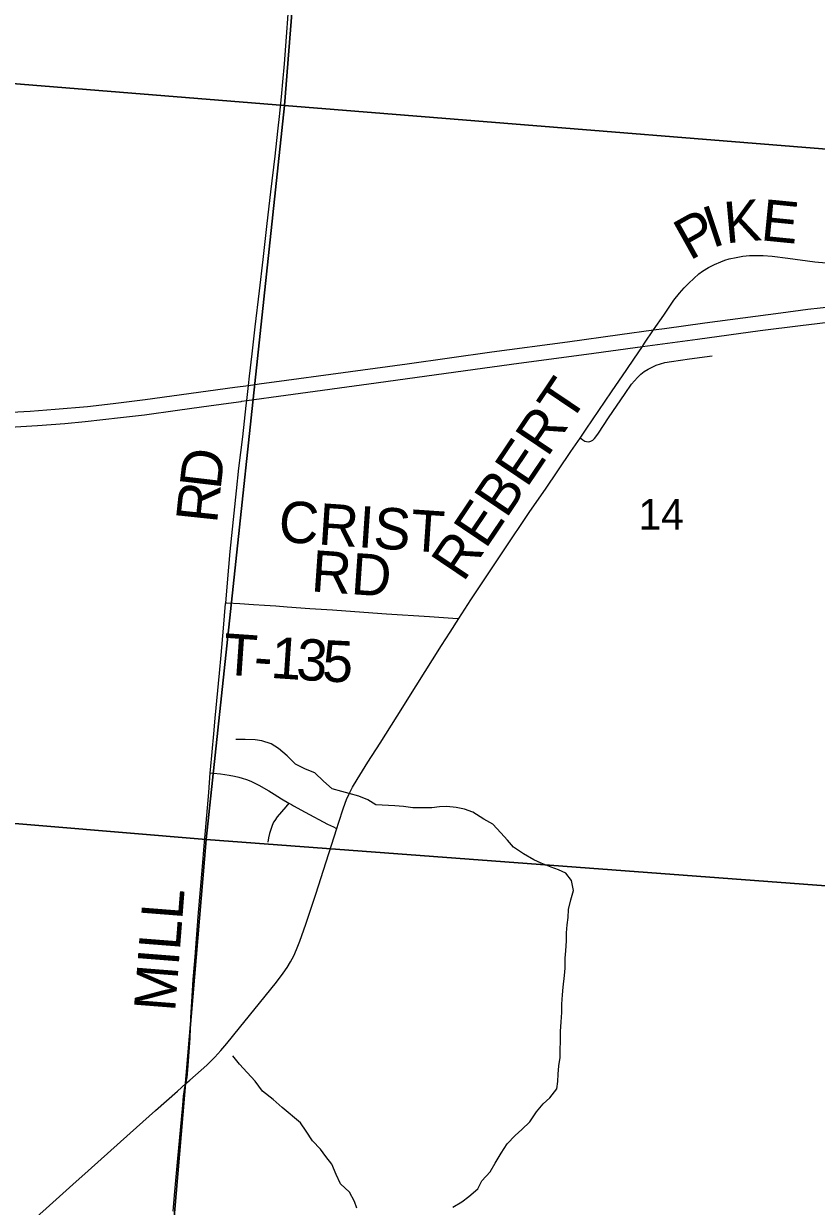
# Model space of a CAD drawing. Extents: x 0 to 34, y 0 to 22.
# Drawn here: x 5.632 to 6.722, y 14.717 to 16.342 of the extents above; entities that cross this region are included whole.
import ezdxf

# ---------------------------------------------------------------- set-up
doc = ezdxf.new("R2010")
doc.units = 0
for name, color, linetype in [('GM_X_County_Road', 7, 'Continuous'), ('GM_X_County_Road_Text', 7, 'Continuous'), ('GM_X_Interstate_Route', 7, 'Continuous'), ('GM_X_Minor_River', 7, 'Continuous'), ('GM_X_Section', 7, 'Continuous'), ('GM_X_Section_Text', 7, 'Continuous'), ('GM_X_Township_Road', 7, 'Continuous'), ('GM_X_Township_Road_Text', 7, 'Continuous')]:
    doc.layers.add(name, color=color, linetype=linetype)

msp = doc.modelspace()

# ---------------------------------------------------------------- linework, layer by layer
at = {"layer": 'GM_X_County_Road'}
for points in [[(6.4706, 15.8808), (6.4825, 15.8983), (6.4855, 15.9027), (6.4979, 15.9209), (6.5118, 15.9412), (6.5259, 15.9617), (6.5336, 15.9715), (6.5397, 15.9786), (6.5462, 15.9854), (6.553, 15.9918), (6.5602, 15.9978), (6.5652, 16.0015), (6.5732, 16.0065), (6.5815, 16.0109), (6.5901, 16.0147), (6.596, 16.0168), (6.602, 16.0186), (6.6112, 16.0206), (6.6204, 16.0221), (6.6298, 16.023), (6.6392, 16.0233), (6.6485, 16.0231), (6.661, 16.0221), (6.6826, 16.0195), (6.7196, 16.0146), (6.735, 16.0131)], [(6.3967, 15.7725), (6.405, 15.7846), (6.44, 15.8359), (6.461, 15.8667), (6.4706, 15.8808)], [(6.2302, 15.5245), (6.2468, 15.5502), (6.2623, 15.5735), (6.2776, 15.5969), (6.2914, 15.6176), (6.3279, 15.6717), (6.3491, 15.7024), (6.3839, 15.7538), (6.3967, 15.7725)], [(6.0623, 15.2362), (6.0646, 15.2436), (6.0714, 15.2643), (6.0758, 15.276), (6.0796, 15.2845), (6.0838, 15.2929), (6.0902, 15.3036), (6.1051, 15.3273), (6.1218, 15.3535), (6.1451, 15.3902), (6.1716, 15.4323), (6.2064, 15.4875), (6.2181, 15.5058), (6.2302, 15.5245)], [(5.8549, 14.8856), (5.8604, 14.8905), (5.8835, 14.9112), (5.8946, 14.922), (5.903, 14.9311), (5.911, 14.9406), (5.9285, 14.9624), (5.9559, 14.9961), (5.9793, 15.0252), (5.9887, 15.0375), (5.994, 15.0451), (5.9988, 15.053), (6.0031, 15.0612), (6.007, 15.0697), (6.0115, 15.0812), (6.0198, 15.1046), (6.0334, 15.1459), (6.0478, 15.1903), (6.0623, 15.2362)], [(5.2834, 14.3675), (5.3102, 14.3924), (5.3892, 14.4668), (5.4048, 14.4812), (5.4275, 14.5022), (5.4459, 14.519), (5.4779, 14.5483), (5.5181, 14.585), (5.5561, 14.6191), (5.5885, 14.6481), (5.6209, 14.6768), (5.6627, 14.7139), (5.6765, 14.7264), (5.6996, 14.7472), (5.7203, 14.766), (5.7783, 14.8176), (5.8131, 14.8486), (5.8434, 14.8753), (5.8549, 14.8856)]]:
    msp.add_lwpolyline(points, dxfattribs=at)
at = {"layer": 'GM_X_Interstate_Route'}
msp.add_line((5.9308, 15.8227), (5.9318, 15.8229), dxfattribs=at)
for points in [[(5.941, 15.8448), (5.9558, 15.8468), (5.9931, 15.852), (6.0541, 15.8602), (6.1592, 15.8746), (6.2755, 15.8908), (6.3793, 15.9048), (6.4515, 15.9148), (6.4979, 15.9209), (6.5128, 15.9229), (6.5683, 15.9306), (6.6728, 15.9446), (6.7098, 15.9493), (6.7777, 15.9568), (6.8405, 15.9634), (6.9002, 15.969), (6.9047, 15.9693)], [(5.9318, 15.8229), (5.9385, 15.8238), (5.9922, 15.8313), (6.1163, 15.8483), (6.2392, 15.8653), (6.3125, 15.8751), (6.4054, 15.8879), (6.4825, 15.8983), (6.5584, 15.9085), (6.6446, 15.92), (6.7, 15.9272), (6.7494, 15.9331), (6.8019, 15.9388), (6.8798, 15.9466), (6.9075, 15.9489)], [(5.5978, 15.807), (5.6405, 15.8094), (5.6749, 15.8119), (5.7194, 15.816), (5.755, 15.8197), (5.7987, 15.8253), (5.9222, 15.8423), (5.941, 15.8448)], [(5.6127, 15.7873), (5.6507, 15.7897), (5.6883, 15.7925), (5.7162, 15.7953), (5.7648, 15.8005), (5.7978, 15.8045), (5.8431, 15.8107), (5.8763, 15.8153), (5.9133, 15.8203), (5.9308, 15.8227)]]:
    msp.add_lwpolyline(points, dxfattribs=at)
at = {"layer": 'GM_X_Minor_River'}
for points in [[(6.1162, 15.2687), (6.105, 15.2753), (6.0925, 15.2804), (6.0793, 15.284), (6.0694, 15.2868), (6.0558, 15.2907), (6.0438, 15.3011), (6.0321, 15.3126), (6.0193, 15.3177), (6.0053, 15.3243), (5.994, 15.3359), (5.982, 15.3459), (5.9722, 15.3524), (5.9594, 15.3564), (5.9499, 15.358), (5.9362, 15.3582), (5.9233, 15.3583)], [(6.2219, 14.7158), (6.234, 14.7233), (6.2439, 14.7304), (6.2561, 14.741), (6.2619, 14.7519), (6.2733, 14.7643), (6.2802, 14.7764), (6.2883, 14.79), (6.2967, 14.8028), (6.3074, 14.8145), (6.3169, 14.8228), (6.3275, 14.8333), (6.3367, 14.8469), (6.3459, 14.8578), (6.3554, 14.8661), (6.365, 14.8786), (6.3662, 14.8884), (6.3666, 14.8986), (6.3678, 14.91), (6.3694, 14.9217), (6.3695, 14.9331), (6.37, 14.943), (6.3701, 14.9574), (6.3709, 14.9706), (6.3718, 14.9835), (6.3719, 14.9949), (6.3727, 15.0074), (6.3736, 15.018), (6.3756, 15.0343), (6.3764, 15.0441), (6.3765, 15.0582), (6.3773, 15.068), (6.3782, 15.0817), (6.3783, 15.093), (6.3791, 15.1036), (6.3803, 15.1139), (6.3808, 15.1249), (6.3839, 15.1381), (6.3878, 15.151), (6.3852, 15.1646), (6.377, 15.1746), (6.3672, 15.1792), (6.357, 15.183), (6.3434, 15.1885), (6.3333, 15.1931), (6.3189, 15.2015), (6.3054, 15.2103), (6.2968, 15.2199), (6.2878, 15.2302), (6.2769, 15.242), (6.2645, 15.2489), (6.2494, 15.2585), (6.2377, 15.2628), (6.2264, 15.2651), (6.2135, 15.2664), (6.2037, 15.2657), (6.1931, 15.2646), (6.1806, 15.2643), (6.167, 15.2644), (6.1541, 15.2661), (6.142, 15.2673), (6.1162, 15.2687)], [(6.0897, 14.7144), (6.0868, 14.7239), (6.0797, 14.7365), (6.0673, 14.748), (6.0614, 14.761), (6.0555, 14.7751), (6.0473, 14.7855), (6.0398, 14.7958), (6.0289, 14.807), (6.02, 14.8204), (6.0122, 14.8318), (5.9873, 14.853), (5.9749, 14.8638), (5.9603, 14.8753), (5.9502, 14.8891), (5.9389, 14.901), (5.9284, 14.9122), (5.9195, 14.9237)]]:
    msp.add_lwpolyline(points, dxfattribs=at)
at = {"layer": 'GM_X_Section'}
for points in [[(5.0487, 17.3219), (6.0711, 17.2462), (5.9902, 16.2292), (4.9634, 16.3122)], [(6.0711, 17.2462), (7.0855, 17.1656), (6.992, 16.1486), (5.9902, 16.2292)], [(4.9634, 16.3122), (5.9902, 16.2292), (5.8825, 15.2209), (4.8743, 15.3051)], [(5.9902, 16.2292), (6.992, 16.1486), (6.9002, 15.1449), (5.8825, 15.2209)], [(4.8743, 15.3051), (5.8825, 15.2209), (5.7982, 14.227), (4.7952, 14.3092), (4.7835, 14.3098)], [(5.8825, 15.2209), (6.9002, 15.1449), (6.8099, 14.1356), (5.8205, 14.2252), (5.7982, 14.227)]]:
    msp.add_lwpolyline(points, close=True, dxfattribs=at)
at = {"layer": 'GM_X_Township_Road'}
for points in [[(5.9096, 15.5462), (5.9139, 15.595), (5.9158, 15.6166), (5.9212, 15.6692), (5.9245, 15.7001), (5.9278, 15.7309), (5.9329, 15.7741), (5.9378, 15.8173), (5.9385, 15.8238), (5.941, 15.8448), (5.9425, 15.8575), (5.9461, 15.8883), (5.9503, 15.9253), (5.9561, 15.9747), (5.9611, 16.0179), (5.9667, 16.0673), (5.9718, 16.1105), (5.9776, 16.1598), (5.9814, 16.1938), (5.9842, 16.2184), (5.9868, 16.2462), (5.9881, 16.2617), (5.9903, 16.2865), (5.9923, 16.3112), (5.9963, 16.367)], [(6.3967, 15.7725), (6.3981, 15.7716), (6.4006, 15.7699), (6.4032, 15.7683), (6.4056, 15.7675), (6.4087, 15.7673), (6.4117, 15.768), (6.4143, 15.7697), (6.4165, 15.7719), (6.4185, 15.7743), (6.4221, 15.7793), (6.4291, 15.7896), (6.436, 15.8), (6.4586, 15.8336), (6.4676, 15.8463), (6.4714, 15.8512), (6.4757, 15.8558), (6.4802, 15.86), (6.4851, 15.8638), (6.4904, 15.8672), (6.4959, 15.87), (6.5016, 15.8725), (6.5075, 15.8746), (6.5135, 15.8761), (6.5227, 15.8778), (6.5474, 15.8812), (6.5782, 15.8854)], [(5.8884, 15.3124), (5.8888, 15.3166), (5.8911, 15.3413), (5.8933, 15.3661), (5.8953, 15.3877), (5.9009, 15.4496), (5.9032, 15.4743), (5.9065, 15.5114), (5.9095, 15.5454), (5.9096, 15.5462)], [(5.9096, 15.5462), (5.9111, 15.5461), (5.929, 15.5452), (5.9476, 15.5439), (5.9631, 15.5428), (5.9787, 15.5418), (5.9942, 15.5407), (6.0252, 15.5385), (6.0563, 15.5363), (6.0749, 15.5349), (6.1308, 15.5308), (6.1899, 15.5271), (6.2283, 15.5246), (6.2302, 15.5245)], [(5.8549, 14.8856), (5.8553, 14.8868), (5.8558, 14.8898), (5.8565, 14.8941), (5.8581, 14.9102), (5.8594, 14.9292), (5.8606, 14.9483), (5.8617, 14.9763), (5.8628, 14.9979), (5.8647, 15.0288), (5.8675, 15.0599), (5.8718, 15.1154), (5.8751, 15.1525), (5.8777, 15.184), (5.88, 15.2123), (5.8817, 15.233), (5.8862, 15.2856), (5.8884, 15.3124)], [(5.8884, 15.3124), (5.893, 15.3119), (5.9023, 15.311), (5.9145, 15.3095), (5.9216, 15.3082), (5.9276, 15.3068), (5.9324, 15.3054), (5.9383, 15.3034), (5.9439, 15.301), (5.955, 15.2956), (5.9688, 15.2878), (5.9763, 15.2831), (5.9865, 15.2767), (5.9965, 15.2708)], [(5.9965, 15.2708), (5.9923, 15.2659), (5.9804, 15.2522), (5.9769, 15.2473), (5.9755, 15.2448), (5.9733, 15.2402), (5.9723, 15.2377), (5.9706, 15.2322), (5.9698, 15.2293), (5.9686, 15.2234), (5.9674, 15.2175)], [(5.9965, 15.2708), (5.9998, 15.2689), (6.003, 15.2672), (6.0188, 15.2587), (6.0497, 15.2421), (6.0577, 15.2382), (6.0611, 15.2367), (6.0623, 15.2362)], [(5.8373, 14.7104), (5.8396, 14.7375), (5.8439, 14.783), (5.8473, 14.8215), (5.8507, 14.856), (5.8517, 14.8684), (5.8529, 14.8777), (5.8535, 14.8808), (5.8549, 14.8856)]]:
    msp.add_lwpolyline(points, dxfattribs=at)

# ---------------------------------------------------------------- texts
at = {"layer": 'GM_X_County_Road_Text'}
for s, height, rotation, p in [('K', 0.0568, 5.1962, (6.5972, 16.0398)), ('E', 0.0568, 354.3619, (6.6441, 16.0443)), ('I', 0.0568, 18.4498, (6.5784, 16.0331)), ('P', 0.0568, 29.137, (6.5475, 16.0156)), ('REBERT', 0.05682, 56.0638, (6.2363, 15.5733))]:
    msp.add_text(s, height=height, rotation=rotation, dxfattribs=at).set_placement(p)
at = {"layer": 'GM_X_Section_Text'}
msp.add_text('14', height=0.04186, rotation=0, dxfattribs=at).set_placement((6.4772, 15.6468))
at = {"layer": 'GM_X_Township_Road_Text'}
for s, height, rotation, p in [('D', 0.0568, 83.304, (5.9024, 15.7004)), ('R', 0.0568, 83.9783, (5.8975, 15.6542)), ('CRIST', 0.05682, 356.1211, (5.981, 15.6301)), ('RD', 0.05682, 356.0542, (6.026, 15.5619)), ('T', 0.0568, 356.0564, (5.9046, 15.4477)), ('1', 0.0568, 356.1234, (5.9703, 15.4431)), ('3', 0.0568, 356.3167, (6.0055, 15.4407)), ('5', 0.0568, 357.1486, (6.0413, 15.4384)), ('-', 0.0568, 356.07, (5.947, 15.4447)), ('MILL', 0.05682, 85.5152, (5.8399, 14.9835))]:
    msp.add_text(s, height=height, rotation=rotation, dxfattribs=at).set_placement(p)

doc.saveas('drawing.dxf')
